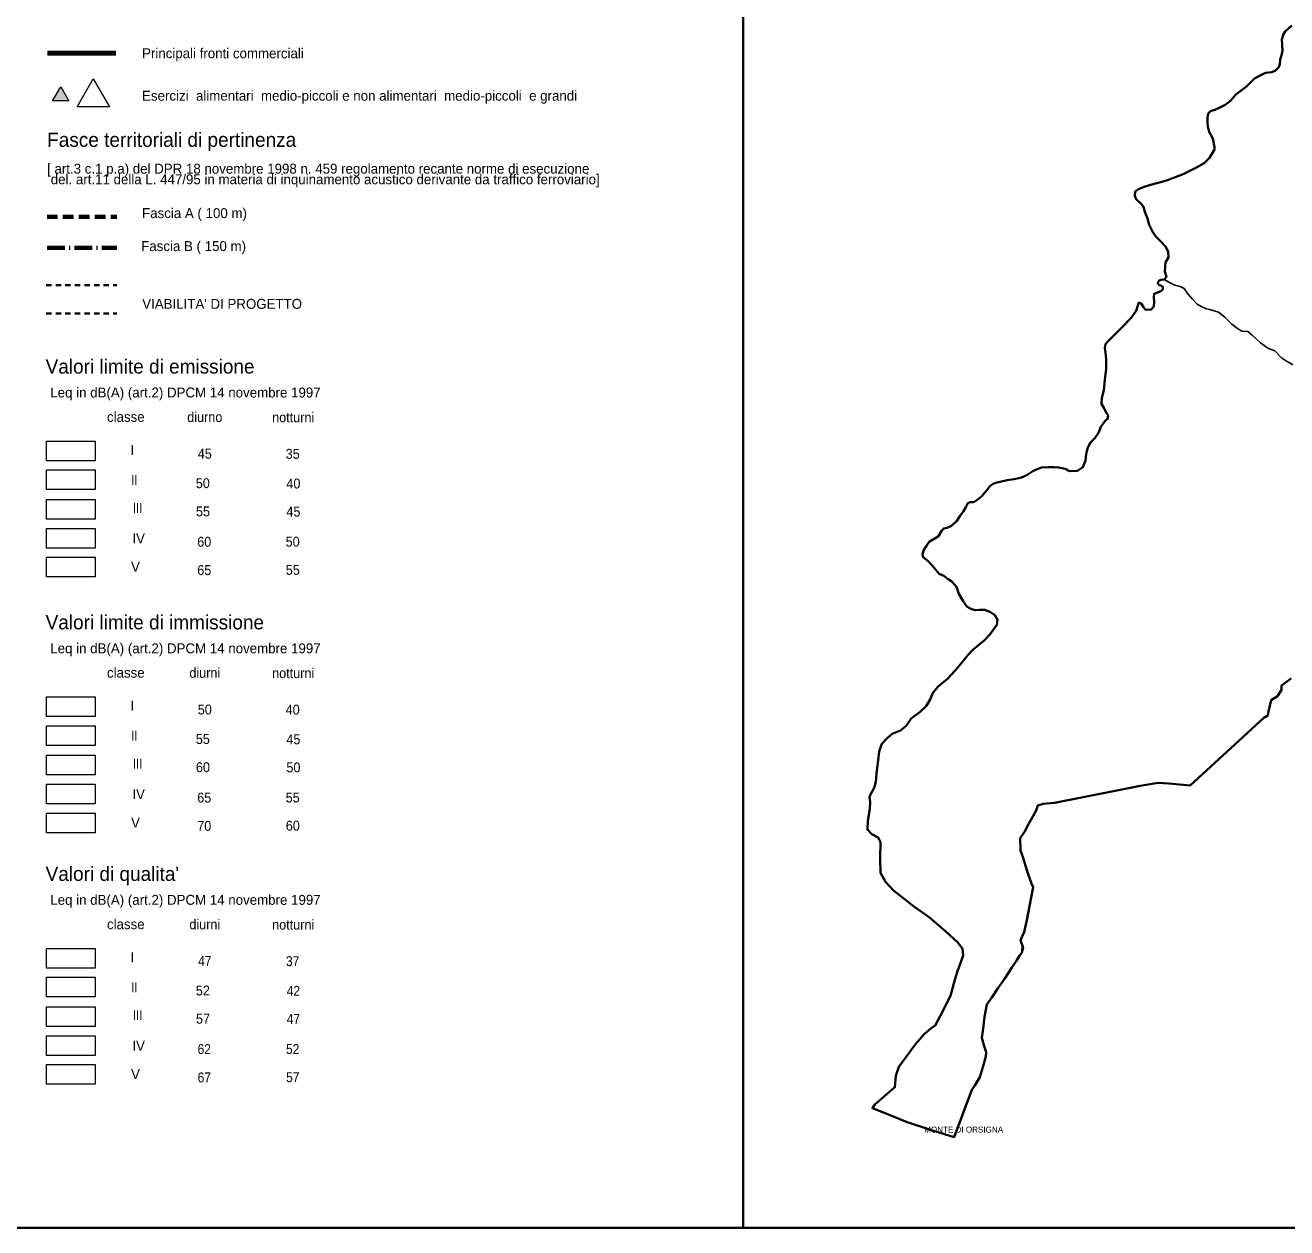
# Model space of a CAD drawing. Extents: x 645880 to 658994, y 884400 to 894744.
# Drawn here: x 648057 to 651612, y 884400 to 887787 of the extents above; entities that cross this region are included whole.
import ezdxf
from ezdxf.enums import TextEntityAlignment as Align

# ---------------------------------------------------------------- set-up
doc = ezdxf.new("R2010")
doc.units = 0
doc.header["$LTSCALE"] = 10
for name, pattern in [('DOT_DASHED', [7.7, 5, -1.2, 0.3, -1.2]), ('MEDIUM_DASHED', [4.5, 3, -1.5]), ('SHORT_DASHED', [2.7, 1.5, -1.2])]:
    doc.linetypes.add(name, pattern=pattern)
for name, color, linetype, lineweight in [('18', 7, 'Continuous', 25), ('59', 7, 'Continuous', 40), ('63', 7, 'Continuous', 35)]:
    doc.layers.add(name, color=color, linetype=linetype, lineweight=lineweight)
doc.layers.add('60', color=7, linetype='Continuous')

msp = doc.modelspace()

# ---------------------------------------------------------------- hatches: boundary and pattern name
at = {"layer": '63'}
msp.add_hatch(color=256, dxfattribs=at).paths.add_polyline_path([(648157.22, 887612.94), (648179.96, 887573.58), (648134.46, 887573.58)])

# ---------------------------------------------------------------- linework, layer by layer
at = {"layer": '18'}
for points in [[(651388.25, 887525.79), (651389.93, 887538.15), (651396.74, 887544.76), (651408.66, 887548.07), (651423.14, 887554.68), (651437.62, 887562.94), (651452.95, 887573.68), (651468.1, 887591.32), (651497.91, 887614.45), (651520.9, 887636.34), (651538.78, 887646.26), (651551.56, 887652.45), (651569.87, 887654.52), (651580.09, 887659.06), (651589.03, 887668.98), (651592.44, 887676.82), (651593.29, 887690.04), (651597.12, 887702.02), (651599.25, 887715.65), (651598.4, 887731.35), (651597.97, 887747.05), (651600.95, 887759.44), (651607.34, 887769.35), (651626, 887785.62)], [(651388.22, 887512.54), (651388.25, 887525.79), (651388.22, 887525.76)], [(651407.84, 887443.18), (651403.55, 887467.93), (651393.33, 887486.93), (651389.08, 887501.8), (651388.22, 887512.54), (651388.25, 887512.57)], [(651266.53, 887070.18), (651272.49, 887078.44), (651268.24, 887093.31), (651269.94, 887119.75), (651278.46, 887132.14), (651277.6, 887148.66), (651270.79, 887162.71), (651256.31, 887177.58), (651241.84, 887192.45), (651234.17, 887204.02), (651223.95, 887224.67), (651218.84, 887242.85), (651212.03, 887261.02), (651207.77, 887275.07), (651200.96, 887283.33), (651187.33, 887296.55), (651183.93, 887306.46), (651184.78, 887318.85), (651194.14, 887325.46), (651209.47, 887331.24), (651227.36, 887337.03), (651249.41, 887343.18), (651275.81, 887350.62), (651320.09, 887367.14), (651355.01, 887385.31), (651378.86, 887398.53), (651394.18, 887413.4), (651407.81, 887436.54), (651407.84, 887436.57)], [(651407.81, 887436.54), (651407.84, 887443.18), (651407.81, 887443.15)], [(651266.53, 887070.18), (651258.02, 887069.35), (651252.06, 887067.7), (651248.65, 887061.92), (651248.68, 887061.95), (651248.68, 887059.47), (651248.65, 887059.44), (651252.06, 887054.48), (651256.31, 887053.66), (651262.27, 887050.35), (651262.3, 887050.38), (651262.3, 887042.95), (651262.27, 887042.92), (651257.17, 887037.96), (651249.5, 887034.66), (651240.98, 887031.35), (651237.58, 887030.53), (651236.73, 887020.61), (651237.58, 887007.39), (651236.73, 886995), (651229.91, 886985.91), (651213.73, 886985.09), (651207.77, 886992.52), (651200.96, 887003.26), (651194.14, 887005.74), (651192.53, 887000.33), (651187.42, 886982.16), (651172.94, 886962.33), (651146.54, 886935.07), (651120.99, 886909.46), (651107.37, 886896.24), (651100.55, 886888.8), (651098.85, 886877.24), (651100.55, 886864.85), (651102.26, 886845.85), (651102.29, 886845.88), (651102.29, 886819.44), (651102.26, 886819.41), (651098.85, 886788.01), (651096.3, 886759.1)], [(651628.51, 886830.06), (651608.29, 886842.59), (651596.73, 886850.3), (651577.47, 886869.57), (651558.22, 886877.28), (651537.99, 886892.7), (651513.92, 886913.9), (651501.4, 886924.5), (651485.03, 886925.46), (651472.51, 886932.21), (651457.1, 886944.73), (651436.88, 886964.97), (651419.54, 886978.46), (651397.4, 886985.21), (651382.95, 886989.06), (651370.43, 886994.84), (651358.88, 887001.59), (651346.36, 887015.08), (651332.88, 887030.5), (651322.28, 887044.95), (651310.73, 887050.73), (651296.28, 887054.59), (651280.87, 887062.3), (651266.53, 887070.18)], [(651628.51, 886830.06), (651608.29, 886842.59), (651596.73, 886850.3), (651577.47, 886869.57), (651558.22, 886877.28), (651537.99, 886892.7), (651513.92, 886913.9), (651501.4, 886924.5), (651485.03, 886925.46), (651472.51, 886932.21), (651457.1, 886944.73), (651436.88, 886964.97), (651419.54, 886978.46), (651397.4, 886985.21), (651382.95, 886989.06), (651370.43, 886994.84), (651358.88, 887001.59), (651346.36, 887015.08), (651332.88, 887030.5), (651322.28, 887044.95), (651310.73, 887050.73), (651296.28, 887054.59), (651280.87, 887062.3), (651266.53, 887070.18)], [(651096.3, 886759.1), (651090.34, 886737.62), (651089.48, 886720.27), (651096.3, 886709.53), (651103.11, 886696.31), (651108.22, 886687.22), (651106.52, 886678.14), (651100.03, 886672.93), (651087.25, 886655.58), (651081.29, 886639.06), (651071.07, 886623.36), (651057.45, 886610.97), (651049.78, 886594.45), (651046.38, 886578.75), (651044.67, 886560.58), (651037.01, 886542.4), (651021.68, 886531.66), (650999.54, 886530.83), (650986.76, 886537.44), (650969.73, 886540.75), (650955.25, 886542.4), (650955.28, 886542.43), (650939.1, 886542.43), (650939.07, 886542.4), (650920.34, 886540.75), (650908.41, 886536.62), (650895.64, 886530.83), (650879.46, 886519.27), (650864.13, 886512.66), (650843.69, 886508.53), (650824.1, 886505.22), (650807.92, 886501.92), (650794.3, 886498.61), (650784.08, 886495.31), (650774.71, 886488.7), (650768.75, 886478.79), (650761.08, 886470.53), (650752.57, 886460.61), (650738.09, 886449.05), (650729.57, 886443.26)], [(650729.57, 886443.26), (650729.6, 886443.29), (650719.38, 886443.29), (650719.35, 886443.26), (650712.54, 886440.78), (650707.43, 886429.22), (650700.62, 886417.65), (650690.4, 886404.43), (650681.88, 886391.22), (650667.4, 886376.34), (650654.63, 886371.39), (650645.26, 886368.91), (650639.56, 886363.56), (650630.19, 886347.86), (650618.27, 886340.43), (650603.79, 886332.17), (650596.13, 886320.6), (650587.61, 886307.38), (650585.06, 886295.82), (650586.76, 886288.38), (650602.09, 886276.81), (650618.27, 886258.64), (650631.9, 886241.29), (650645.52, 886235.51), (650657.45, 886226.42), (650667.67, 886219.81), (650681.29, 886204.94), (650687.25, 886185.11), (650700.03, 886164.46), (650710.25, 886149.59), (650723.02, 886142.15), (650734.94, 886139.67), (650746.02, 886140.5), (650746.05, 886140.53), (650760.52, 886140.53), (650760.49, 886140.5), (650776.67, 886133.89), (650788.6, 886124.8), (650796.26, 886112.41), (650794.56, 886097.54)], [(650794.56, 886097.54), (650775.82, 886071.93), (650758.79, 886053.75), (650728.13, 886028.14), (650712.69, 886012.9), (650684.58, 885978.21), (650656.48, 885946.81), (650629.23, 885924.51), (650614.75, 885906.33), (650607.08, 885887.33), (650596.01, 885869.15), (650578.98, 885852.63), (650553.43, 885834.46), (650538.95, 885813.8), (650523.62, 885800.58), (650499.78, 885790.67), (650485.3, 885779.1), (650470.82, 885762.58), (650463.16, 885741.1), (650459.75, 885708.88), (650455.49, 885679.14), (650453.79, 885656.01), (650448.68, 885638.66), (650438.46, 885619.66), (650435.91, 885612.22), (650437.61, 885599), (650436.76, 885579.18), (650431.59, 885545.92), (650429.88, 885521.14), (650442.66, 885508.75), (650460.54, 885498.83), (650467.36, 885485.62), (650465.65, 885439.35), (650466.5, 885399.7), (650480.98, 885374.09), (650503.12, 885350.13), (650563.59, 885303.04), (650604.47, 885274.95), (650652.16, 885233.64), (650684.52, 885203.07)], [(650861.72, 885462.44), (650860.87, 885497.14), (650872.79, 885514.49), (650883.86, 885536.79), (650905.15, 885574.8), (650910.26, 885588.84), (650925.59, 885593.8), (650957.1, 885596.28), (651032.89, 885611.15), (651141.9, 885633.45), (651198.96, 885644.19), (651249.01, 885653.06), (651339.29, 885645.62), (651546.84, 885836.1), (651557.92, 885842.71), (651567.28, 885885.67), (651585.17, 885897.24), (651597.09, 885914.59), (651597.09, 885926.98), (651623.49, 885946.81)], [(650684.52, 885203.07), (650698.15, 885184.9), (650699.85, 885166.72), (650694.02, 885150.8), (650683.8, 885122.71), (650676.13, 885097.93), (650664.21, 885053.32), (650636.11, 884997.96), (650620.78, 884969.05), (650608.85, 884960.79), (650590.97, 884945.92), (650565.42, 884917), (650539.02, 884881.48), (650518.58, 884853.39), (650510.06, 884827.78), (650507.51, 884795.56), (650450.6, 884746.76), (650444.24, 884736.48), (650484.52, 884720.71), (650542.47, 884697.41), (650607.48, 884675.47), (650674.61, 884654.91), (650724.08, 884788.58), (650747.19, 884824.1), (650763.37, 884882.34), (650764.22, 884894.73), (650752.3, 884934.8), (650759.96, 884993.87), (650766.33, 885028.73), (650798.26, 885075.41), (650851.06, 885153.89), (650864.69, 885175.37), (650865.97, 885196.85), (650861.71, 885208.42), (650871.93, 885232.38), (650891.52, 885329.86), (650897.48, 885358.78), (650879.6, 885406.69), (650868.53, 885441.79), (650861.72, 885462.44)]]:
    msp.add_lwpolyline(points, dxfattribs=at)
at = {"layer": '59'}
for points in [[(651607.34, 887769.35), (651626, 887785.62)], [(651183.93, 887306.46), (651184.78, 887318.85), (651194.14, 887325.46), (651209.47, 887331.24), (651227.36, 887337.03), (651249.41, 887343.18), (651275.81, 887350.62), (651320.09, 887367.14), (651355.01, 887385.31), (651378.86, 887398.53), (651394.18, 887413.4), (651407.81, 887436.54), (651407.81, 887443.15), (651403.55, 887467.93), (651393.33, 887486.93), (651389.08, 887501.8), (651388.22, 887512.54), (651388.22, 887525.76), (651389.93, 887538.15), (651396.74, 887544.76), (651408.66, 887548.07), (651423.14, 887554.68), (651437.62, 887562.94), (651452.95, 887573.68), (651468.1, 887591.32), (651497.91, 887614.45), (651520.9, 887636.34), (651538.78, 887646.26), (651551.56, 887652.45), (651569.87, 887654.52), (651580.09, 887659.06), (651589.03, 887668.98), (651592.44, 887676.82), (651593.29, 887690.04), (651597.12, 887702.02), (651599.25, 887715.65), (651598.4, 887731.35), (651597.97, 887747.05), (651600.95, 887759.44), (651607.34, 887769.35)], [(651172.94, 886962.33), (651187.42, 886982.16), (651192.53, 887000.33), (651194.14, 887005.74), (651200.96, 887003.26), (651207.77, 886992.52), (651213.73, 886985.09), (651229.91, 886985.91), (651236.73, 886995), (651237.58, 887007.39), (651236.73, 887020.61), (651237.58, 887030.53), (651240.98, 887031.35), (651249.5, 887034.66), (651257.17, 887037.96), (651262.27, 887042.92), (651262.27, 887050.35), (651256.31, 887053.66), (651252.06, 887054.48), (651248.65, 887059.44), (651248.65, 887061.92), (651252.06, 887067.7), (651258.02, 887069.35), (651266.53, 887070.18), (651272.49, 887078.44), (651268.24, 887093.31), (651269.94, 887119.75), (651278.46, 887132.14), (651277.6, 887148.66), (651270.79, 887162.71), (651256.31, 887177.58), (651241.84, 887192.45), (651234.17, 887204.02), (651223.95, 887224.67), (651218.84, 887242.85), (651212.03, 887261.02), (651207.77, 887275.07), (651200.96, 887283.33), (651187.33, 887296.55), (651183.93, 887306.46)], [(650807.92, 886501.92), (650824.1, 886505.22), (650843.69, 886508.53), (650864.13, 886512.66), (650879.46, 886519.27), (650895.64, 886530.83), (650908.41, 886536.62), (650920.34, 886540.75), (650939.07, 886542.4), (650955.25, 886542.4), (650969.73, 886540.75), (650986.76, 886537.44), (650999.54, 886530.83), (651021.68, 886531.66), (651037.01, 886542.4), (651044.67, 886560.58), (651046.38, 886578.75), (651049.78, 886594.45), (651057.45, 886610.97), (651071.07, 886623.36), (651081.29, 886639.06), (651087.25, 886655.58), (651100.03, 886672.93), (651106.52, 886678.14), (651108.22, 886687.22), (651103.11, 886696.31), (651096.3, 886709.53), (651089.48, 886720.27), (651090.34, 886737.62), (651096.3, 886759.1), (651098.85, 886788.01), (651102.26, 886819.41), (651102.26, 886845.85), (651100.55, 886864.85), (651098.85, 886877.24), (651100.55, 886888.8), (651107.37, 886896.24), (651120.99, 886909.46), (651146.54, 886935.07), (651172.94, 886962.33)], [(650760.49, 886140.5), (650746.02, 886140.5), (650734.94, 886139.67), (650723.02, 886142.15), (650710.25, 886149.59), (650700.03, 886164.46), (650687.25, 886185.11), (650681.29, 886204.94), (650667.67, 886219.81), (650657.45, 886226.42), (650645.52, 886235.51), (650631.9, 886241.29), (650618.27, 886258.64), (650602.09, 886276.81), (650586.76, 886288.38), (650585.06, 886295.82), (650587.61, 886307.38), (650596.13, 886320.6), (650603.79, 886332.17), (650618.27, 886340.43), (650630.19, 886347.86), (650639.56, 886363.56), (650645.26, 886368.91), (650654.63, 886371.39), (650667.4, 886376.34), (650681.88, 886391.22), (650690.4, 886404.43), (650700.62, 886417.65), (650707.43, 886429.22), (650712.54, 886440.78), (650719.35, 886443.26), (650729.57, 886443.26), (650738.09, 886449.05), (650752.57, 886460.61), (650761.08, 886470.53), (650768.75, 886478.79), (650774.71, 886488.7), (650784.08, 886495.31), (650794.3, 886498.61), (650807.92, 886501.92)], [(650503.12, 885350.13), (650480.98, 885374.09), (650466.5, 885399.7), (650465.65, 885439.35), (650467.36, 885485.62), (650460.54, 885498.83), (650442.66, 885508.75), (650429.88, 885521.14), (650431.59, 885545.92), (650436.76, 885579.18), (650437.61, 885599), (650435.91, 885612.22), (650438.46, 885619.66), (650448.68, 885638.66), (650453.79, 885656.01), (650455.49, 885679.14), (650459.75, 885708.88), (650463.16, 885741.1), (650470.82, 885762.58), (650485.3, 885779.1), (650499.78, 885790.67), (650523.62, 885800.58), (650538.95, 885813.8), (650553.43, 885834.46), (650578.98, 885852.63), (650596.01, 885869.15), (650607.08, 885887.33), (650614.75, 885906.33), (650629.23, 885924.51), (650656.48, 885946.81), (650684.58, 885978.21), (650712.69, 886012.9), (650728.13, 886028.14), (650758.79, 886053.75), (650775.82, 886071.93), (650794.56, 886097.54), (650796.26, 886112.41), (650788.6, 886124.8), (650776.67, 886133.89), (650760.49, 886140.5)], [(651623.49, 885946.81), (651597.09, 885926.98), (651597.09, 885914.59), (651585.17, 885897.24), (651567.28, 885885.67), (651560.47, 885854.28), (651557.92, 885842.71), (651546.84, 885836.1), (651339.29, 885645.62), (651278.82, 885651.41), (651249.01, 885653.06), (651231.98, 885650.58), (651198.96, 885644.19), (651141.9, 885633.45), (651032.89, 885611.15), (650957.1, 885596.28), (650925.59, 885593.8), (650910.26, 885588.84), (650905.15, 885574.8), (650883.86, 885536.79), (650872.79, 885514.49), (650860.87, 885497.14), (650861.72, 885462.44), (650868.53, 885441.79), (650879.6, 885406.69), (650891.52, 885371.17), (650897.48, 885358.78), (650891.52, 885329.86), (650878.74, 885266.25), (650871.93, 885232.38), (650865.12, 885218.33), (650861.71, 885208.42), (650865.97, 885196.85), (650868.52, 885188.59), (650864.69, 885175.37), (650858.3, 885165.87), (650851.06, 885153.89), (650836.58, 885132.41), (650817, 885101.43)], [(650817, 885101.43), (650798.26, 885075.41), (650780.8, 885048.56), (650766.33, 885028.73), (650759.96, 884993.87), (650755.71, 884960.41), (650752.3, 884934.8), (650759.11, 884911.67), (650764.22, 884894.73), (650763.37, 884882.34), (650755.28, 884852.19), (650747.19, 884824.1), (650733.14, 884800.14), (650724.08, 884788.58), (650674.61, 884654.91), (650607.48, 884675.47), (650542.47, 884697.41), (650484.52, 884720.71), (650444.24, 884736.48), (650450.6, 884746.76), (650507.51, 884795.56), (650510.06, 884827.78), (650518.58, 884853.39), (650539.02, 884881.48), (650565.42, 884917), (650590.97, 884945.92), (650608.85, 884960.79), (650620.78, 884969.05), (650636.11, 884997.96), (650664.21, 885053.32), (650676.13, 885097.93), (650683.8, 885122.71), (650694.02, 885150.8), (650699.85, 885166.72), (650698.15, 885184.9), (650684.52, 885203.07), (650652.16, 885233.64), (650604.47, 885274.95), (650563.59, 885303.04), (650503.12, 885350.13)]]:
    msp.add_lwpolyline(points, dxfattribs=at)
at = {"layer": '63', "lineweight": 80}
msp.add_line((648312.82, 887707.94), (648119.66, 887707.94), dxfattribs=at)
at = {"layer": '63', "linetype": 'MEDIUM_DASHED', "lineweight": 70}
msp.add_line((648118.66, 887246.82), (648315.5, 887246.82), dxfattribs=at)
at = {"layer": '63', "linetype": 'DOT_DASHED', "lineweight": 70}
msp.add_line((648118.66, 887159.38), (648315.5, 887159.38), dxfattribs=at)
at = {"layer": '63', "linetype": 'SHORT_DASHED', "lineweight": 40}
for p, q in [((648116.14, 887054.84), (648315.5, 887054.84)), ((648116.14, 886974.84), (648315.5, 886974.84))]:
    msp.add_line(p, q, dxfattribs=at)
at = {"layer": '63', "lineweight": 40}
for points in [[(647980.32, 884399.72), (650080.32, 884399.72), (650080.32, 889588.16), (647980.32, 889588.16)], [(656397.82, 884399.72), (650080.32, 884399.72), (650080.32, 889588.16), (656397.82, 889588.16)]]:
    msp.add_lwpolyline(points, close=True, dxfattribs=at)
at = {"layer": '63', "lineweight": 13}
for points in [[(648157.22, 887612.94), (648179.96, 887573.58), (648134.46, 887573.58)], [(648249.08, 887635.56), (648294.56, 887556.8), (648203.62, 887556.8)], [(648117.48, 886615.64), (648254.56, 886615.64), (648254.56, 886560.2), (648117.48, 886560.2)], [(648117.48, 886534.24), (648254.56, 886534.24), (648254.56, 886478.8), (648117.48, 886478.8)], [(648117.48, 886451.08), (648254.56, 886451.08), (648254.56, 886395.64), (648117.48, 886395.64)], [(648117.48, 886369.64), (648254.56, 886369.64), (648254.56, 886314.2), (648117.48, 886314.2)], [(648117.48, 886288.2), (648254.56, 886288.2), (648254.56, 886232.76), (648117.48, 886232.76)], [(648117.48, 885895.12), (648254.56, 885895.12), (648254.56, 885839.68), (648117.48, 885839.68)], [(648117.48, 885813.72), (648254.56, 885813.72), (648254.56, 885758.28), (648117.48, 885758.28)], [(648117.48, 885730.56), (648254.56, 885730.56), (648254.56, 885675.12), (648117.48, 885675.12)], [(648117.48, 885649.12), (648254.56, 885649.12), (648254.56, 885593.68), (648117.48, 885593.68)], [(648117.48, 885567.68), (648254.56, 885567.68), (648254.56, 885512.24), (648117.48, 885512.24)], [(648117.48, 885186.7), (648254.56, 885186.7), (648254.56, 885131.26), (648117.48, 885131.26)], [(648117.48, 885105.3), (648254.56, 885105.3), (648254.56, 885049.86), (648117.48, 885049.86)], [(648117.48, 885022.14), (648254.56, 885022.14), (648254.56, 884966.7), (648117.48, 884966.7)], [(648117.48, 884940.7), (648254.56, 884940.7), (648254.56, 884885.26), (648117.48, 884885.26)], [(648117.48, 884859.26), (648254.56, 884859.26), (648254.56, 884803.82), (648117.48, 884803.82)]]:
    msp.add_lwpolyline(points, close=True, dxfattribs=at)

# ---------------------------------------------------------------- texts
at = {"layer": '60'}
msp.add_text('MONTE DI ORSIGNA', height=17, dxfattribs=at).set_placement((650701.2, 884667.68), align=Align.CENTER)
at = {"layer": '63'}
for s, height, p in [('Principali fronti commerciali', 28, (648386.48, 887693.87)), ('Esercizi  alimentari  medio-piccoli e non alimentari  medio-piccoli  e grandi', 28, (648386.48, 887574.27)), ('Fasce territoriali di pertinenza', 40, (648119.08, 887444.31)), ('[ art.3 c.1 p.a) del DPR 18 novembre 1998 n. 459 regolamento recante norme di esecuzione', 28, (648118.92, 887368.81)), (' del. art.11 della L. 447/95 in materia di inquinamento acustico derivante da traffico ferroviario]', 28, (648118.92, 887338.81)), ('Fascia A ( 100 m)', 28, (648386.48, 887243.59)), ('Fascia B ( 150 m)', 28, (648383.98, 887150.73)), ("VIABILITA' DI PROGETTO", 28, (648386.92, 886988.03)), ('Valori limite di emissione', 40, (648114.74, 886805.71)), ('Leq in dB(A) (art.2) DPCM 14 novembre 1997', 28, (648127.9, 886738.35)), ('Valori limite di immissione', 40, (648114.74, 886085.19)), ('Leq in dB(A) (art.2) DPCM 14 novembre 1997', 28, (648127.9, 886017.83)), ("Valori di qualita'", 40, (648114.74, 885376.75)), ('Leq in dB(A) (art.2) DPCM 14 novembre 1997', 28, (648127.9, 885309.39))]:
    msp.add_text(s, height=height, dxfattribs=at).set_placement(p)
for s, p in [('classe', (648340.72, 886669.71)), ('I', (648358.76, 886576.65)), ('IV', (648376.93, 886327.53)), ('V', (648367.94, 886247.65)), ('classe', (648340.72, 885949.19)), ('I', (648358.76, 885856.13)), ('IV', (648376.93, 885607.01)), ('V', (648367.94, 885527.13)), ('classe', (648340.72, 885240.75)), ('I', (648358.76, 885147.69)), ('IV', (648376.93, 884898.57)), ('V', (648367.94, 884818.69))]:
    msp.add_text(s, height=28, dxfattribs=at).set_placement(p, align=Align.CENTER)
for s, width, p in [('diurno', 0.95, (648563.18, 886669.31)), ('notturni', 0.95, (648812.29, 886668.43)), ('45', 0.95, (648563.18, 886565.99)), ('35', 0.95, (648810.85, 886565.63)), ('II', 0.8, (648364.64, 886492.01)), (' 50', 0.95, (648552.74, 886482.91)), ('40', 0.95, (648812.82, 886482.03)), ('III', 0.85, (648373.85, 886413.41)), (' 55', 0.95, (648553.1, 886403.47)), ('45', 0.95, (648812.9, 886402.95)), ('60', 0.95, (648561.66, 886317.87)), ('50', 0.95, (648810.82, 886318.15)), ('65', 0.95, (648561.78, 886238.07)), ('55', 0.95, (648811.18, 886238.91)), ('diurni', 0.95, (648563.16, 885948.79)), ('notturni', 0.95, (648812.29, 885947.91)), ('50', 0.95, (648563.18, 885845.47)), ('40', 0.95, (648810.85, 885845.11)), ('II', 0.8, (648364.64, 885771.49)), (' 55', 0.95, (648552.74, 885762.39)), ('45', 0.95, (648812.82, 885761.51)), ('III', 0.85, (648373.85, 885692.89)), (' 60', 0.95, (648553.1, 885682.95)), ('50', 0.95, (648812.9, 885682.43)), ('65', 0.95, (648561.66, 885597.35)), ('55', 0.95, (648810.82, 885597.63)), ('70', 0.95, (648561.78, 885517.55)), ('60', 0.95, (648811.18, 885518.39)), ('diurni', 0.95, (648563.16, 885240.35)), ('notturni', 0.95, (648812.29, 885239.47)), ('47', 0.9, (648563.16, 885137.03)), ('37', 0.9, (648810.84, 885136.67)), ('II', 0.8, (648364.64, 885063.05)), (' 52', 0.95, (648552.75, 885053.95)), ('42', 0.9, (648812.8, 885053.07)), ('III', 0.85, (648373.85, 884984.45)), (' 57', 0.95, (648553.11, 884974.51)), ('47', 0.9, (648812.88, 884973.99)), ('62', 0.9, (648561.64, 884888.91)), ('52', 0.9, (648810.8, 884889.19)), ('67', 0.9, (648561.76, 884809.11)), ('57', 0.9, (648811.16, 884809.95))]:
    msp.add_text(s, height=28, dxfattribs=dict(at, width=width)).set_placement(p, align=Align.CENTER)

doc.saveas('drawing.dxf')
